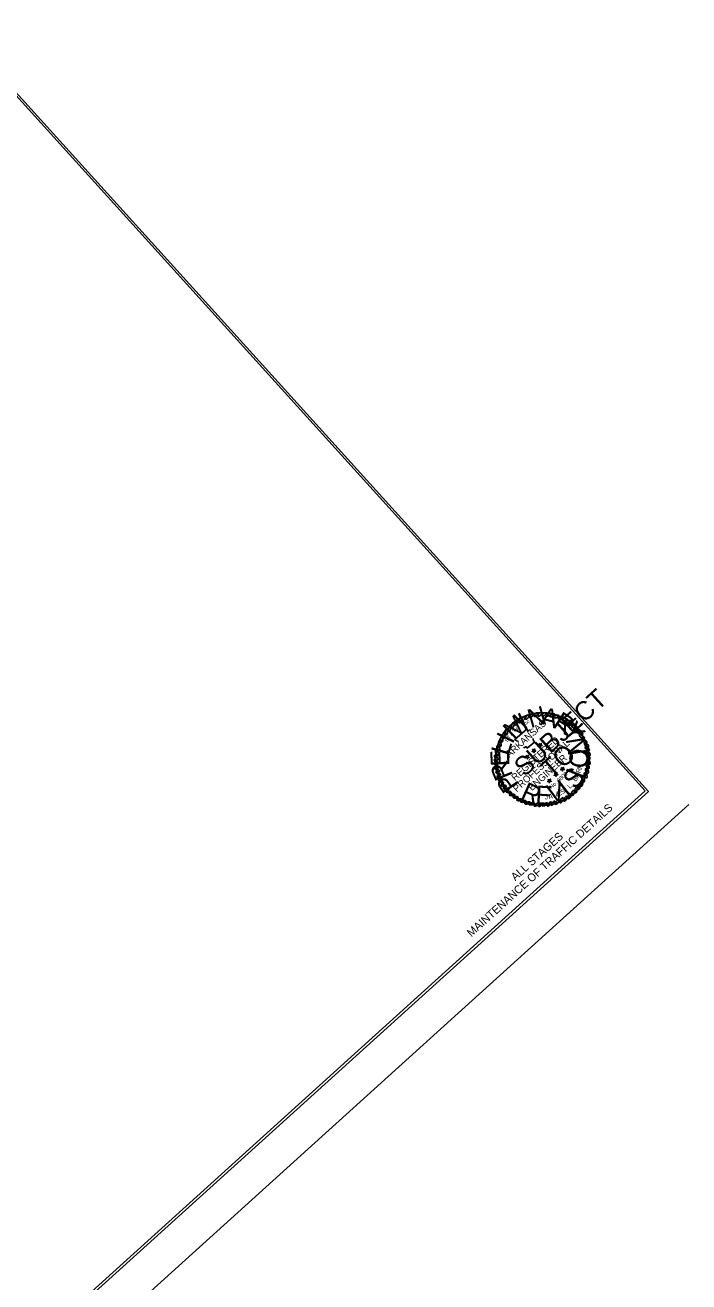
# Model space of a CAD drawing. Extents: x 1307930 to 1312775, y 238372 to 242903.
# Drawn here: x 1312112 to 1312775, y 241610 to 242866 of the extents above; entities that cross this region are included whole.
import ezdxf

# ---------------------------------------------------------------- set-up
doc = ezdxf.new("R2010")
doc.units = 0
doc.layers.add('R_Base', color=7, linetype='Continuous')

msp = doc.modelspace()

# ---------------------------------------------------------------- linework, layer by layer
at = {"layer": 'R_Base'}
for p, q in [((1312731.4, 242101.1), (1312042.3, 242862.9)), ((1312731.4, 242101.1), (1311559, 241040.5)), ((1311469.7, 240906.6), (1312774.9, 242087.4))]:
    msp.add_line(p, q, dxfattribs=at)
for points in [[(1311559.3, 241037.3), (1312734.6, 242100.6), (1312042, 242866.3), (1310866.6, 241802.9)], [(1312625.2, 242148.3), (1312626.5, 242147.5), (1312627.6, 242148.5), (1312627.3, 242147.2), (1312628.6, 242146.4), (1312627.1, 242146.2), (1312626.8, 242144.8), (1312626.2, 242146.2), (1312624.8, 242145.9), (1312625.9, 242146.9)], [(1312612.2, 242136.5), (1312613.5, 242135.7), (1312614.6, 242136.7), (1312614.2, 242135.3), (1312615.5, 242134.5), (1312614.1, 242134.4), (1312613.8, 242133), (1312613.1, 242134.4), (1312611.7, 242134.1), (1312612.8, 242135.1)], [(1312618.9, 242142.8), (1312620.1, 242142.1), (1312621.1, 242143), (1312620.9, 242141.6), (1312622.1, 242140.9), (1312620.7, 242140.7), (1312620.4, 242139.3), (1312619.8, 242140.6), (1312618.3, 242140.5), (1312619.4, 242141.5)], [(1312647.3, 242124.6), (1312648.6, 242123.8), (1312649.7, 242124.7), (1312649.3, 242123.5), (1312650.6, 242122.6), (1312649.2, 242122.5), (1312648.9, 242121), (1312648.2, 242122.4), (1312646.9, 242122.2), (1312648, 242123.2)], [(1312634.3, 242112.8), (1312635.6, 242111.9), (1312636.7, 242112.9), (1312636.3, 242111.6), (1312637.6, 242110.8), (1312636.1, 242110.7), (1312635.8, 242109.2), (1312635.2, 242110.6), (1312633.8, 242110.4), (1312634.9, 242111.4)], [(1312640.9, 242119), (1312642.2, 242118.3), (1312643.2, 242119.2), (1312642.9, 242117.8), (1312644.2, 242117.2), (1312642.8, 242116.9), (1312642.4, 242115.6), (1312641.9, 242116.9), (1312640.4, 242116.8), (1312641.5, 242117.7)]]:
    msp.add_lwpolyline(points, close=True, dxfattribs=at)
for points in [[(1312604, 242150.6), (1312601, 242152.4), (1312613.4, 242163), (1312614, 242160.5), (1312615.9, 242162.1), (1312616, 242161.8)], [(1312619.3, 242153.5), (1312619.3, 242151.5), (1312621, 242150.1), (1312613.6, 242143.8), (1312612.2, 242145.3), (1312610.9, 242144.1), (1312610, 242145.1)]]:
    msp.add_lwpolyline(points, dxfattribs=at)
msp.add_circle((1312628.3, 242132.9), 46.3, dxfattribs=at)
for centre, major_axis, ratio in [((1312606.1, 242171.4), (-0.74, -2.32), 0.475469), ((1312609.7, 242173.3), (-1.22, -2.1), 0.475469), ((1312613.4, 242174.8), (-1.47, -1.94), 0.475469), ((1312617.5, 242176.1), (-1.66, -1.78), 0.475469), ((1312622.1, 242177.3), (-1.66, -1.78), 0.475469), ((1312626.2, 242177.6), (-1.84, -1.59), 0.475469), ((1312630.1, 242177.5), (-2.12, -1.45), 0.451028), ((1312634.6, 242177.3), (-2.31, -1.3), 0.436264), ((1312638.6, 242176.6), (-2.5, -1.19), 0.418512), ((1312642.6, 242175.4), (-2.78, -0.65), 0.40589), ((1312647.1, 242174.2), (-2.83, -0.35), 0.40589), ((1312592.8, 242160.1), (-0.29, -3.1), 0.348728), ((1312595.8, 242163.1), (-0.42, -2.42), 0.44237), ((1312599.1, 242166.6), (-0.74, -2.32), 0.475469), ((1312602.6, 242169.2), (-0.74, -2.32), 0.475469), ((1312651, 242172.2), (-2.85, -0.05), 0.40589), ((1312654.6, 242170.2), (-2.85, -0.05), 0.40589), ((1312657.8, 242167.9), (-2.85, 0.09), 0.40589), ((1312660.9, 242165.1), (-2.81, 0.49), 0.40589), ((1312663.7, 242162.1), (-2.7, 0.92), 0.40589), ((1312586.2, 242148.2), (0.81, -2.73), 0.329518), ((1312588.2, 242152.7), (0.16, -2.85), 0.329518), ((1312590.2, 242156.5), (0.13, -2.85), 0.329518), ((1312666.4, 242158.8), (-2.6, 1.16), 0.40589), ((1312668.3, 242155.2), (-2.4, 1.55), 0.40589), ((1312670.8, 242151.1), (-2.26, 1.74), 0.40589), ((1312672.7, 242147), (-2.03, 2), 0.40589), ((1312582.5, 242134.2), (1.27, -2.55), 0.391724), ((1312583.3, 242139.2), (1.27, -2.55), 0.394697), ((1312584.7, 242143.6), (1.27, -2.55), 0.375751), ((1312673.5, 242143.2), (-2.03, 2), 0.40589), ((1312674.4, 242138.8), (-1.81, 2.2), 0.40589), ((1312674.4, 242134.7), (-1.55, 2.39), 0.40589), ((1312582.6, 242130.2), (1.91, -2.12), 0.322879), ((1312582.8, 242126.4), (1.91, -2.12), 0.322879), ((1312583.6, 242122.2), (2.42, -1.51), 0.322879), ((1312673.2, 242121.2), (-0.92, 2.7), 0.40589), ((1312673.8, 242126.1), (-1.35, 2.51), 0.40589), ((1312674.7, 242130.2), (-1.55, 2.39), 0.40589), ((1312584.5, 242118.5), (2.42, -1.51), 0.322879), ((1312585.8, 242114.4), (2.42, -1.51), 0.322879), ((1312587.4, 242110.3), (2.42, -1.51), 0.322879), ((1312667.8, 242108.5), (0.18, 2.85), 0.40589), ((1312669.7, 242112.8), (-0.28, 2.84), 0.40589), ((1312671.9, 242116.7), (-0.83, 2.73), 0.40589), ((1312589.9, 242106.3), (2.75, -0.77), 0.322879), ((1312592.4, 242103.2), (2.75, -0.77), 0.322879), ((1312595.1, 242099.9), (2.75, -0.77), 0.322879), ((1312598.5, 242097.1), (2.84, -0.22), 0.322879), ((1312655.7, 242096), (0.85, 2.72), 0.40589), ((1312659.1, 242099), (0.85, 2.72), 0.40589), ((1312662.1, 242101.7), (0.6, 2.79), 0.40589), ((1312665.1, 242105.2), (0.38, 2.83), 0.40589), ((1312602, 242094.7), (2.84, -0.22), 0.322879), ((1312605.9, 242092.2), (2.85, 0.05), 0.322879), ((1312609.7, 242090.6), (2.83, 0.36), 0.322879), ((1312613.8, 242089.1), (2.74, 0.8), 0.322879), ((1312618.2, 242088.2), (2.74, 0.8), 0.322879), ((1312623, 242087.4), (2.47, 1.43), 0.322879), ((1312627.1, 242087.2), (2.47, 1.43), 0.322879), ((1312631.4, 242087.6), (2.47, 1.43), 0.322879), ((1312635.6, 242088), (1.95, 2.08), 0.322879), ((1312639.4, 242088.8), (1.95, 2.08), 0.322879), ((1312643.3, 242089.8), (1.95, 2.08), 0.40589), ((1312647.8, 242091.6), (1.53, 2.41), 0.40589), ((1312651.8, 242093.4), (1.53, 2.41), 0.40589)]:
    msp.add_ellipse(centre, major_axis=major_axis, ratio=ratio, dxfattribs=at)

# ---------------------------------------------------------------- texts
for s, height, rotation, p in [('SUBJECT', 18.62, 42.1319, (1312610.8, 242114.5)), ('M', 18.6, 44.8262, (1312600.5, 242151.4)), ('I', 18.6, 25.51, (1312610, 242160.4)), ('N', 18.6, 15.8519, (1312616.9, 242163.7)), ('A', 18.6, 346.8775, (1312625.6, 242167.1)), ('R', 18.6, 327.5613, (1312637.9, 242165.5)), ('ARKANSAS', 6.91, 42.1319, (1312595.8, 242133.9)), ('T', 3.45, 43.2337, (1312600.7, 242158.9)), ('E', 3.45, 38.6138, (1312603.7, 242161.6)), ('O', 3.45, 24.754, (1312610.1, 242166)), ('F', 3.45, 20.1341, (1312613.7, 242167.6)), ('Y', 18.6, 308.2451, (1312647.8, 242161)), ('L', 18.6, 73.8006, (1312594.9, 242135.4)), ('I', 18.6, 64.1425, (1312598.8, 242147.2)), ('S', 3.45, 61.7133, (1312593.7, 242149.4)), ('T', 3.45, 57.0934, (1312595.7, 242152.7)), ('A', 3.45, 47.8536, (1312597.8, 242155.9)), ('REGISTERED', 6.91, 42.1319, (1312601.5, 242110.7)), ('PROFESSIONAL', 6.907, 42.1319, (1312603.1, 242099.5)), ('N', 18.6, 99.2697, (1312673.2, 242138.2)), ('E', 18.6, 93.1168, (1312595.9, 242126.1)), ('ENGINEER', 6.91, 42.1319, (1312618.2, 242100.7)), ('TO', 18.62, 42.1319, (1312637.8, 242112.6)), ('O', 18.6, 78.7074, (1312672.2, 242122.3)), ('R', 18.6, 112.4331, (1312599.7, 242116.4)), ('S', 18.6, 47.8639, (1312661.1, 242101.9)), ('I', 18.6, 68.4262, (1312668.7, 242112.2)), ('R', 4.8, 71.7535, (1312666.5, 242118.4)), ('R', 4.8, 77.3539, (1312667.9, 242122.8)), ('P', 18.6, 124.7408, (1312606.1, 242107.5)), ('V', 18.6, 17.0204, (1312636.8, 242088.3)), ('No. 9808', 3.95, 42.1319, (1312637.8, 242102.8)), ('I', 18.6, 37.5828, (1312652.9, 242094.9)), ('B', 4.8, 60.5527, (1312662.3, 242110)), ('A', 4.8, 66.1531, (1312664.6, 242113.9)), ('R', 18.6, 335.8958, (1312605.7, 242093.5)), ('E', 18.6, 356.4581, (1312621.4, 242088)), ('A', 4.8, 10.149, (1312635.1, 242092.9)), ('M', 4.8, 15.7494, (1312639.8, 242093.9)), ('E', 4.8, 26.9502, (1312644.7, 242095.6)), ('S', 4.8, 32.5506, (1312648.6, 242097.5)), ('L', 4.8, 43.7515, (1312656.1, 242103)), ('.', 4.8, 49.3519, (1312659.2, 242106.2)), ('MAINTENANCE OF TRAFFIC DETAILS', 8, 42.1319, (1312557.7, 241954.8)), ('J', 4.8, 4.5486, (1312631.1, 242092.5)), ('ALL STAGES', 8, 42.1319, (1312601.6, 242010.7))]:
    msp.add_text(s, height=height, rotation=rotation, dxfattribs=at).set_placement(p)

doc.saveas('drawing.dxf')
